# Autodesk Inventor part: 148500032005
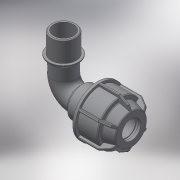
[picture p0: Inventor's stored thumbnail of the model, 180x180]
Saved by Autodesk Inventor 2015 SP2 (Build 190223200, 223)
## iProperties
Created: 2017-08
Part Number: 148500032005
Material: Generic
Description: PLASSON L.14 90° ELBOW MALE ADAPTOR (SILVER) 32-1/2"
Document SubType Name: Modeling
Designer: KIM
Density: 1 g/cm^3
Appearance: Default
Author: KIM
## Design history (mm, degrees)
derived "148500.ipt"
feature "Solid1::148500.ipt"
feature "Solid2::148500.ipt"
tag "TaggingFeature1"
body "Solid1"
body "Solid2"
other parameters: "d1" = 32, "d2" = 56, "d4" = 15 deg, "d5" = 36.96, "d6" = 12.1968, "d10" = 61, "d16" = 32.64, "d17" = 2.8, "d22" = 51.2, "d24" = 2.8, "d25" = 54.9, "d26" = 45.75, "d27" = 2.8, "d28" = 135 deg, "d29" = 1.68, "d31" = 1.6, "d46" = 150 deg, "d49" = 3.05, "d50" = 0, "d58" = 0.96, "d61" = 360 deg, "d63" = 19.2, "d94" = 49, "d96" = 23.0505, "d97" = 17, "d98" = 16.764, "d99" = 19.59292, "d100" = 135 deg, "d108" = 1.6, "d112" = 22.1, "d113" = 75, "d114" = 66.08, "d115" = 19.59292, "d116" = 45 deg, "d117" = 0, "d118" = 0, "d119" = 20.955, "d120" = 17, "d121" = 25.146, "d122" = 17.85, "d123" = 1, "d_" = 32, "R_" = 20.955, "E_" = 61, "A_" = 75, "l_" = 56, "l_2" = 17, "A_1" = 49
